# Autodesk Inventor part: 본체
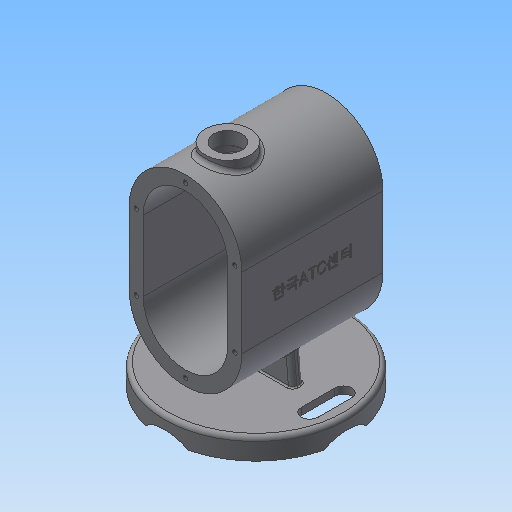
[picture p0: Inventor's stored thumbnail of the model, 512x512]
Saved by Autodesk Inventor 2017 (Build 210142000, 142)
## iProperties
Created: 2016-12
Part Number: 본체
Material: 일반
Document SubType Name: Modeling
Designer: mduedu
Density: 1 g/cm^3
Appearance: 기본값
Author: mduedu
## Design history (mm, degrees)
sketch "스케치1"
  geometry: L1 (40, -25)-(40, 25); L2 (-40, 25)-(-40, -25); L3 (-40, -25)-(40, 25); L4 (40, -25)-(-40, 25); L5 (0, 25)-(0, -25); A1 r 40 centre (0, 25) between (40, 25) and (-40, 25); A2 r 40 centre (0, -25) between (-40, -25) and (40, -25); 1 further point
  constraints: 10 end point, 4 point on circle, 3 tangent, 2 centre point, 2 midpoint, 2 parallel, 1 vertical
  dimensions: "d0" = 130 dimension on A2 A1; "d2" = 80 distance between parallel lines of L1 L2
extrude "돌출1" new body sketch "스케치1" stored distance "d3" = 100; taper "d4" = 0 deg
feature "쉘1" dims "d5" = 10
sketch "스케치2"
  geometry: L1 (-75, 65)-(-90, 65); L2 (-90, 65)-(-90, 0); L3 (-75, 0)-(-75, 65); L4 (-75, 0)-(-90, 0); 1 further point
  constraints: 8 end point, 1 horizontal, 1 horizontal alignment, 1 parallel, 1 perpendicular
  dimensions: "d6" = 90 distance from line of L2 point (0, 0); "d83" = 15 distance of L1.start L1.end; "d84" = 130 diameter of L1 L4
revolve "회전1" sketch "스케치2" stored, may be unused: angle "d85" = 90 deg
fillet "모깎기5" dims "d86" = 3
hole "구멍6" diameter "d89" = 120; stored, may be unused: countersink angle "d93" = 90 deg, drill point angle "d95" = 0 deg; dims "d87" = 10, "d88" = 10, "d90" = 6, "d91" = 4, "d92" = 2, "d94" = 10
sketch "스케치15"
  geometry: L1 (-90, -60)-(-90, 60) reference; A1 r 21.75 centre (-105.75, 0) between (-90, -15) and (-90, 15); 3 further points
  constraints: 3 point on circle, 2 point on line, 1 centre point, 1 horizontal alignment, 1 midpoint
  dimensions: "d119" = 30 distance of A1.start A1.end; "d120" = 6 distance of point (-84, 0) point (-90, 0)
extrude "돌출6" cut sketch "스케치15" stored distance "d97" = 10; taper "d98" = 0 deg
sketch "스케치5"
  geometry: L1 (4, -30)-(-4, -30); L2 (-4, -30)-(-4, 30); L3 (-4, 30)-(4, 30); L4 (4, 30)-(4, -30); L5 (4, -30)-(-4, 30); L6 (-4, -30)-(4, 30); 3 further points
  constraints: 12 end point, 3 midpoint, 2 parallel, 1 coincident, 1 horizontal, 1 perpendicular
  dimensions: "d22" = 8 distance of L2.end L3.end; "d24" = 60 distance of L1.end L2.end
extrude "돌출3" join sketch "스케치5" stored distance "d25" = 80; taper "d26" = 0 deg
feature "면 기울기1" dims angle "d27" = 5 deg
sketch "스케치6"
  geometry: L1 (-28.115, -53.453)-(-30, -75); L2 (-62, -75)-(62, -75) reference; A1 r 40 centre (0, -25) between (-40, -25) and (40, -25) reference; 1 further point
  constraints: 2 end point, 1 point on circle, 1 point on line
  dimensions: "d28" = 30 horizontal distance of A1.centre L1.end; "d102" = 85 deg angle of L2 L1
feature "리브1" sketch "스케치6" dims "d30" = 1, "d31" = 8, "d32" = 0, "d33" = 0, "d34" = 1, "d35" = 1
fillet "모깎기2" dims "d36" = 3
fillet "모깎기3" dims "d37" = 1, "d38" = 1
node "작업 평면1"
sketch "스케치9"
  geometry: 1 further point
sketch "스케치7"
  geometry: L1 (40, 50)-(-40, 50) reference; C1 r 16 at (0, 20); 1 further point
  constraints: 1 centre point, 1 vertical alignment
  dimensions: "d40" = 32 diameter of C1; "d41" = 30 distance from line of C1.centre L1
extrude "돌출4" join sketch "스케치7" stored distance "d42" = 80; taper "d43" = 0 deg
hole "구멍2" diameter "d46" = 20; stored, may be unused: countersink angle "d50" = 90 deg, drill point angle "d52" = 118 deg; dims "d44" = 10, "d45" = 10, "d47" = 6, "d48" = 4, "d49" = 2, "d51" = 8
fillet "모깎기4" dims "d53" = 3
node "작업 평면2"
sketch "스케치8"
  geometry: C1 r 16 at (0, 0) reference; C2 r 15 at (0, 0); 1 further point
  constraints: 1 centre point, 1 coincident
  dimensions: "d55" = 30 diameter of C2
extrude "돌출5" cut sketch "스케치8" stored distance "d56" = 80; taper "d57" = 0 deg
chamfer "모따기1" distance "d58" = 1; stored, may be unused: second distance "d59" = 2, angle "d60" = 45 deg
sketch "스케치10"
  geometry: 2 further points
  constraints: 1 coincident, 1 other
feature "엠보싱1" sketch "스케치10" dims "d0" = 130, "d2" = 80, "d61" = 0.5, "d62" = 0
sketch "스케치11"
  geometry: 1 further point
hole "구멍3" sketch "스케치11" at (0, 60) diameter "d63" = 3.242; stored, may be unused: countersink angle "d67" = 90 deg, drill point angle "d69" = 120 deg; dims "d64" = 8.6, "d65" = 4, "d66" = 2, "d68" = 10.6
sketch "스케치12"
  geometry: 1 further point
hole "구멍5" sketch "스케치12" at (0, 60) diameter "d70" = 3.242; stored, may be unused: countersink angle "d74" = 90 deg, drill point angle "d76" = 120 deg; dims "d71" = 8.6, "d72" = 4, "d73" = 2, "d75" = 10.6
sketch "스케치16"
  geometry: L1 (0, 0)-(0, 50); L2 (-56, 12)-(-56, -12); L3 (-44, 12)-(-44, -12); L4 (-50, -12)-(-50, 12); A1 r 50 centre (0, 0) between (0, 50) and (-50, 0); A2 r 6 centre (-50, 12) between (-44, 12) and (-56, 12); A3 r 6 centre (-50, -12) between (-56, -12) and (-44, -12); 1 further point
  constraints: 8 end point, 6 point on circle, 4 tangent, 3 centre point, 3 parallel, 1 coincident, 1 equal radius, 1 horizontal alignment, 1 midpoint, 1 vertical
  dimensions: "d103" = 100 diameter of A1; "d121" = 6 radius of A2; "d122" = 24 distance of L4.start L4.end
extrude "돌출7" cut sketch "스케치16" stored distance "d123" = 10; taper "d124" = 0 deg
node "솔리드1"
pattern_circular "원형 패턴1" dims angle "d100" = 90 deg
mirror "대칭1"
pattern_linear "직사각형 패턴1"
pattern_linear "직사각형 패턴2"
mirror "대칭2"
sketch "스케치13"
  geometry: L1 (-40, 25)-(-40, -25) reference; L2 (40, -25)-(40, 25) reference; L3 (35, 25)-(35, -25); L4 (-35, -25)-(-35, 25); A1 r 40 centre (0, 25) between (40, 25) and (-40, 25) reference; A2 r 40 centre (0, -25) between (-40, -25) and (40, -25) reference; A3 r 35 centre (0, 25) between (35, 25) and (-35, 25); A4 r 35 centre (0, -25) between (-35, -25) and (35, -25); 2 further points
  constraints: 5 point on circle, 4 end point, 2 centre point, 3 other
  dimensions: "d77" = 5 distance between parallel lines of L3 L2
sketch "스케치14"
  geometry: L1 (-40, 25)-(-40, -25) reference; L2 (40, -25)-(40, 25) reference; L3 (35, 25)-(35, -25); L4 (-35, -25)-(-35, 25); A1 r 40 centre (0, 25) between (40, 25) and (-40, 25) reference; A2 r 40 centre (0, -25) between (-40, -25) and (40, -25) reference; A3 r 35 centre (0, 25) between (35, 25) and (-35, 25); A4 r 35 centre (0, -25) between (-35, -25) and (35, -25); 2 further points
  constraints: 5 point on circle, 4 end point, 2 centre point, 3 other
  dimensions: "d80" = 5 distance between parallel lines of L2 L3
